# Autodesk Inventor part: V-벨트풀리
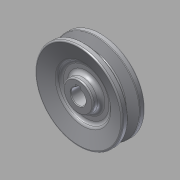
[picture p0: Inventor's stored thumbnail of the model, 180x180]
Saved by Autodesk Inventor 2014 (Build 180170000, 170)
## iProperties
Created: 2016-08
Part Number: V-벨트풀리
Material: 알루미늄 6061
Document SubType Name: Modeling
Designer: mduedu
Density: 2.71 g/cm^3
Appearance: Aluminum - Flat
Author: mduedu
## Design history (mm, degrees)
sketch "스케치1"
  geometry: L1 (0, 9.5)-(0, -9.5); L2 (0, 9.5)-(35, 9.5); L3 (35, 9.5)-(35, 4.825); L4 (35, 4.825)-(26, 2.074); L5 (26, 2.074)-(26, 0); L6 (0, 0)-(26, 0); L7 (0, -9.5)-(35, -9.5); L8 (35, -9.5)-(35, -4.825); L9 (35, -4.825)-(26, -2.074); L10 (26, -2.074)-(26, 0); L11 (32.3, 9.5)-(32.3, -9.5); 3 further points
  constraints: 22 end point, 6 point on line, 4 perpendicular, 3 symmetric about line, 1 coincident, 1 horizontal alignment, 1 midpoint, 1 parallel, 1 vertical
  dimensions: "d0" = 19 distance of L1.start L1.end; "d2" = 70 diameter of L8 L1; "d4" = 6.3 distance between parallel lines of L10 L11; "d5" = 2.7 distance between parallel lines of L11 L8; "d6" = 8 distance of point (32.3, -4) point (32.3, 4); "d7" = 34 deg angle of L9 L4
revolve "회전1" sketch "스케치1" stored, may be unused: angle "d8" = 90 deg
sketch "스케치2"
  geometry: L1 (-2, 0)-(2, 0); L2 (2, 0)-(2, 7.8); L3 (2, 7.8)-(-2, 7.8); L4 (-2, 7.8)-(-2, 0); C1 r 6 at (0, 0); 2 further points
  constraints: 8 end point, 2 coincident, 2 parallel, 1 centre point, 1 horizontal, 1 midpoint, 1 perpendicular
  dimensions: "d9" = 12 diameter of C1; "d11" = 4 distance of L2.end L3.end; "d12" = 7.8 distance of L1.end L2.end
extrude "돌출1" cut sketch "스케치2" stored distance "d13" = 10; taper "d14" = 0 deg
sketch "스케치3"
  geometry: L1 (35, 4.825)-(26, 2.074) reference; L2 (26, 2.074)-(26, -2.074) reference; L3 (0, 0)-(26, 0); L4 (35, 9.5)-(35, 4.825) reference; L5 (-35, 9.5)-(35, 9.5) reference; L6 (35, 9.5)-(21, 5.22); L7 (21, 5.22)-(21, 3); L8 (21, 3)-(12, 3); L9 (12, 3)-(12, 9.5); L10 (0, 9.5)-(0, -9.5); L11 (5.657, -9.5)-(-6, -9.5) reference; L12 (12, 9.5)-(35, 9.5)
  constraints: 14 end point, 3 midpoint, 2 parallel, 2 perpendicular, 2 point on line, 1 collinear, 1 horizontal
  dimensions: "d15" = 3 distance between parallel lines of L3 L8; "d17" = 42 diameter of L7 L10; "d18" = 24 diameter of L9 L10
revolve "회전2" sketch "스케치3" stored, may be unused: angle "d19" = 90 deg
fillet "모깎기1" dims "d20" = 0.5, "d21" = 1, "d22" = 1
fillet "모깎기2" dims "d23" = 3
fillet "모깎기3" dims "d24" = 3
fillet "모깎기4" dims "d25" = 3
chamfer "모따기1" distance "d26" = 0.5; stored, may be unused: second distance "d27" = 2, angle "d28" = 45 deg
fillet "모깎기5" dims "d29" = 1
node "솔리드1"
mirror "대칭1"
